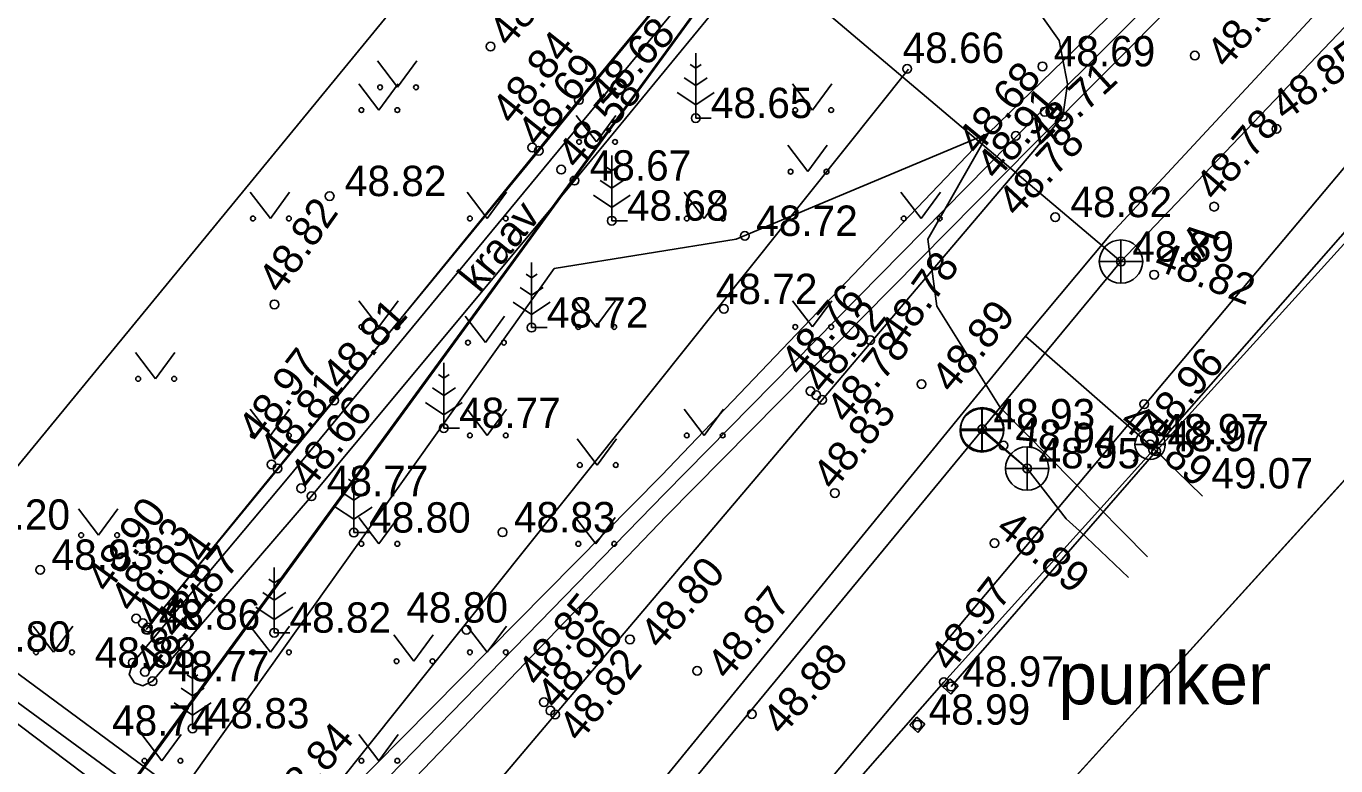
# Model space of a CAD drawing. Extents: x 640876 to 641418, y 6455595 to 6456085.
# Drawn here: x 641190.78 to 641220.97, y 6455862.86 to 6455879.91 of the extents above; entities that cross this region are included whole.
import ezdxf

# ---------------------------------------------------------------- set-up
doc = ezdxf.new("R2010")
doc.units = 0
for name, color, linetype in [('AED', 7, 'Continuous'), ('HALJASTUS', 7, 'Continuous'), ('HOONE', 7, 'Continuous'), ('KKAEV', 7, 'Continuous'), ('KORGUS', 7, 'Continuous'), ('KTRASS', 7, 'Continuous'), ('MOOTKORG', 7, 'Continuous'), ('MOOTMPUNKT', 7, 'Continuous'), ('MOOTPIIR', 7, 'Continuous'), ('PIIR', 7, 'Continuous'), ('PUU', 7, 'Continuous'), ('SITRASS', 7, 'Continuous'), ('TEE', 7, 'Continuous'), ('TTRASS', 7, 'Continuous'), ('VEEKOGU', 7, 'Continuous'), ('VKAEV', 7, 'Continuous'), ('VTRASS', 7, 'Continuous')]:
    doc.layers.add(name, color=color, linetype=linetype)

msp = doc.modelspace()

# ---------------------------------------------------------------- linework, layer by layer
at = {"layer": 'AED'}
for p, q in [((641211.91, 6455864.679), (641212.074, 6455864.867)), ((641211.91, 6455864.679), (641212.098, 6455864.515)), ((641212.074, 6455864.867), (641212.262, 6455864.703)), ((641212.098, 6455864.515), (641212.262, 6455864.703)), ((641211.146, 6455863.796), (641211.31, 6455863.984)), ((641211.146, 6455863.796), (641211.334, 6455863.632)), ((641211.31, 6455863.984), (641211.498, 6455863.82)), ((641211.334, 6455863.632), (641211.498, 6455863.82))]:
    msp.add_line(p, q, dxfattribs=at)
msp.add_lwpolyline([(641221.825, 6455875.625), (641216.829, 6455870.111), (641212.099, 6455864.686)], dxfattribs=at)
at = {"layer": 'HALJASTUS'}
for p, q in [((641198.876, 6455879.109), (641199.339, 6455878.502)), ((641199.339, 6455878.502), (641199.785, 6455879.109)), ((641198.445, 6455878.583), (641198.909, 6455877.977)), ((641198.909, 6455877.977), (641199.354, 6455878.583)), ((641208.445, 6455878.583), (641208.909, 6455877.977)), ((641208.909, 6455877.977), (641209.354, 6455878.583)), ((641203.462, 6455877.849), (641203.926, 6455877.242)), ((641203.926, 6455877.242), (641204.371, 6455877.849)), ((641208.338, 6455877.164), (641208.802, 6455876.557)), ((641208.802, 6455876.557), (641209.247, 6455877.164)), ((641195.945, 6455876.083), (641196.409, 6455875.477)), ((641196.409, 6455875.477), (641196.854, 6455876.083)), ((641200.945, 6455876.083), (641201.409, 6455875.477)), ((641201.409, 6455875.477), (641201.854, 6455876.083)), ((641205.945, 6455876.083), (641206.409, 6455875.477)), ((641206.409, 6455875.477), (641206.854, 6455876.083)), ((641210.945, 6455876.083), (641211.409, 6455875.477)), ((641211.409, 6455875.477), (641211.854, 6455876.083)), ((641198.445, 6455873.583), (641198.909, 6455872.977)), ((641198.909, 6455872.977), (641199.354, 6455873.583)), ((641203.445, 6455873.583), (641203.909, 6455872.977)), ((641203.909, 6455872.977), (641204.354, 6455873.583)), ((641208.445, 6455873.583), (641208.909, 6455872.977)), ((641208.909, 6455872.977), (641209.354, 6455873.583)), ((641200.901, 6455873.223), (641201.365, 6455872.616)), ((641201.365, 6455872.616), (641201.81, 6455873.223)), ((641193.299, 6455872.387), (641193.763, 6455871.781)), ((641193.763, 6455871.781), (641194.208, 6455872.387)), ((641195.945, 6455871.083), (641196.409, 6455870.477)), ((641196.409, 6455870.477), (641196.854, 6455871.083)), ((641200.945, 6455871.083), (641201.409, 6455870.477)), ((641201.409, 6455870.477), (641201.854, 6455871.083)), ((641205.945, 6455871.083), (641206.409, 6455870.477)), ((641206.409, 6455870.477), (641206.854, 6455871.083)), ((641203.48, 6455870.401), (641203.944, 6455869.794)), ((641203.944, 6455869.794), (641204.389, 6455870.401)), ((641191.986, 6455868.784), (641192.449, 6455868.177)), ((641192.449, 6455868.177), (641192.895, 6455868.784)), ((641198.445, 6455868.583), (641198.909, 6455867.977)), ((641198.909, 6455867.977), (641199.354, 6455868.583)), ((641203.445, 6455868.583), (641203.909, 6455867.977)), ((641203.909, 6455867.977), (641204.354, 6455868.583)), ((641190.945, 6455866.083), (641191.409, 6455865.477)), ((641191.409, 6455865.477), (641191.854, 6455866.083)), ((641195.945, 6455866.083), (641196.409, 6455865.477)), ((641196.409, 6455865.477), (641196.854, 6455866.083)), ((641199.256, 6455865.877), (641199.719, 6455865.271)), ((641199.719, 6455865.271), (641200.165, 6455865.877)), ((641200.945, 6455866.083), (641201.409, 6455865.477)), ((641201.409, 6455865.477), (641201.854, 6455866.083)), ((641193.445, 6455863.583), (641193.909, 6455862.977)), ((641193.909, 6455862.977), (641194.354, 6455863.583)), ((641198.445, 6455863.583), (641198.909, 6455862.977)), ((641198.909, 6455862.977), (641199.354, 6455863.583))]:
    msp.add_line(p, q, dxfattribs=at)
for centre in [(641198.938, 6455878.502), (641199.767, 6455878.502), (641198.508, 6455877.977), (641199.336, 6455877.977), (641208.508, 6455877.977), (641209.336, 6455877.977), (641203.525, 6455877.242), (641204.354, 6455877.242), (641208.401, 6455876.557), (641209.229, 6455876.557), (641196.008, 6455875.477), (641196.836, 6455875.477), (641201.008, 6455875.477), (641201.836, 6455875.477), (641206.008, 6455875.477), (641206.836, 6455875.477), (641211.008, 6455875.477), (641211.836, 6455875.477), (641198.508, 6455872.977), (641199.336, 6455872.977), (641203.508, 6455872.977), (641204.336, 6455872.977), (641208.508, 6455872.977), (641209.336, 6455872.977), (641200.964, 6455872.616), (641201.793, 6455872.616), (641193.362, 6455871.781), (641194.191, 6455871.781), (641196.008, 6455870.477), (641196.836, 6455870.477), (641201.008, 6455870.477), (641201.836, 6455870.477), (641206.008, 6455870.477), (641206.836, 6455870.477), (641203.543, 6455869.794), (641204.371, 6455869.794), (641192.048, 6455868.177), (641192.877, 6455868.177), (641198.508, 6455867.977), (641199.336, 6455867.977), (641203.508, 6455867.977), (641204.336, 6455867.977), (641191.008, 6455865.477), (641191.836, 6455865.477), (641196.008, 6455865.477), (641196.836, 6455865.477), (641199.318, 6455865.271), (641200.147, 6455865.271), (641201.008, 6455865.477), (641201.836, 6455865.477), (641193.508, 6455862.977), (641194.336, 6455862.977), (641198.508, 6455862.977), (641199.336, 6455862.977)]:
    msp.add_circle(centre, 0.055, dxfattribs=at)
at = {"layer": 'HOONE'}
msp.add_lwpolyline([(641149.742, 6455963.717), (641189.36, 6455931.349), (641178.797, 6455918.488), (641209.743, 6455893.117), (641188.509, 6455867.25), (641179.281, 6455874.809), (641167.4, 6455884.521), (641162.961, 6455888.191)], dxfattribs=at)
at = {"layer": 'KKAEV'}
for p, q in [((641216.017, 6455873.983), (641216.017, 6455874.983)), ((641215.517, 6455874.483), (641216.517, 6455874.483)), ((641212.81, 6455870.093), (641212.81, 6455871.093)), ((641212.819, 6455870.118), (641212.819, 6455871.118)), ((641212.31, 6455870.593), (641213.31, 6455870.593)), ((641212.319, 6455870.618), (641213.319, 6455870.618)), ((641213.851, 6455869.215), (641213.851, 6455870.215)), ((641213.351, 6455869.715), (641214.351, 6455869.715))]:
    msp.add_line(p, q, dxfattribs=at)
for centre in [(641216.017, 6455874.483), (641212.81, 6455870.593), (641212.819, 6455870.618), (641213.851, 6455869.715)]:
    msp.add_circle(centre, 0.5, dxfattribs=at)
at = {"layer": 'KORGUS'}
for centre in [(641201.486, 6455879.442), (641217.721, 6455879.232), (641211.088, 6455878.926), (641203.523, 6455878.209), (641214.258, 6455877.939), (641214.527, 6455877.902), (641206.213, 6455877.792), (641214.674, 6455877.825), (641219.599, 6455877.542), (641213.592, 6455877.382), (641202.447, 6455877.113), (641202.594, 6455877.038), (641203.114, 6455876.603), (641203.419, 6455876.35), (641197.776, 6455875.993), (641218.162, 6455875.75), (641214.502, 6455875.508), (641204.278, 6455875.427), (641207.347, 6455875.076), (641216.779, 6455874.182), (641196.501, 6455873.497), (641206.865, 6455873.393), (641202.431, 6455872.961), (641210.235, 6455872.675), (641211.418, 6455871.659), (641197.878, 6455871.284), (641208.859, 6455871.496), (641208.994, 6455871.405), (641209.127, 6455871.296), (641216.554, 6455871.196), (641200.41, 6455870.647), (641213.306, 6455870.244), (641216.758, 6455870.138), (641196.438, 6455869.807), (641196.571, 6455869.717), (641197.119, 6455869.257), (641209.421, 6455869.149), (641197.36, 6455869.076), (641198.335, 6455868.236), (641201.763, 6455868.243), (641213.1, 6455867.995), (641191.105, 6455867.378), (641193.315, 6455866.255), (641193.472, 6455866.148), (641193.547, 6455866), (641193.585, 6455866.047), (641196.5, 6455865.929), (641200.932, 6455865.997), (641204.699, 6455865.775), (641193.238, 6455865.238), (641193.519, 6455865.029), (641206.247, 6455865.05), (641193.694, 6455864.808), (641211.935, 6455864.789), (641202.716, 6455864.327), (641202.864, 6455864.132), (641202.972, 6455864.043), (641207.507, 6455864.054), (641194.617, 6455863.722)]:
    msp.add_circle(centre, 0.1, dxfattribs=at)
at = {"layer": 'KTRASS'}
for p, q in [((641216.017, 6455874.483), (641207.241, 6455881.908)), ((641212.819, 6455870.618), (641216.017, 6455874.483)), ((641212.819, 6455870.618), (641213.854, 6455869.717))]:
    msp.add_line(p, q, dxfattribs=at)
for points in [[(641216.001, 6455874.47), (641231.848, 6455891.086), (641231.899, 6455887.222)], [(641199.925, 6455854.961), (641212.81, 6455870.593), (641213.851, 6455869.715), (641214.751, 6455868.557), (641215.062, 6455868.275), (641216.191, 6455867.2)]]:
    msp.add_lwpolyline(points, dxfattribs=at)
at = {"layer": 'MOOTMPUNKT'}
for centre in [(641214.205, 6455878.984), (641216.017, 6455874.483), (641212.819, 6455870.618), (641216.688, 6455870.271), (641216.829, 6455870.111), (641213.854, 6455869.717), (641193.574, 6455865.998), (641212.099, 6455864.686), (641211.322, 6455863.808)]:
    msp.add_circle(centre, 0.1, dxfattribs=at)
at = {"layer": 'MOOTPIIR'}
msp.add_lwpolyline([(641060.916, 6455895.936), (641100.061, 6455950.482), (641099.586, 6455952.159), (641069.132, 6455984.035), (641066.132, 6455988.623), (641076.463, 6456005.049), (641230.642, 6456010.048), (641237.36, 6455995.24), (641237.24, 6455992.81), (641236.258, 6455990.888), (641229.041, 6455971.315), (641203.026, 6455909.57), (641225.257, 6455906.847), (641239.512, 6455898.491), (641200.195, 6455851.697), (641192.016, 6455859.099), (641169.785, 6455829.138), (641192.025, 6455807.568), (641252.96, 6455758.075), (641231.388, 6455736.74), (641191.474, 6455775.975), (641152.419, 6455787.914), (641136.351, 6455788.307), (641049.066, 6455856.043)], dxfattribs=at)
at = {"layer": 'PIIR'}
for points in [[(641222.58, 6455998.61), (641237.36, 6455995.24), (641235.34, 6455991.29), (641228.11, 6455971.68), (641220.5, 6455953.19), (641213.41, 6455936.25), (641201.58, 6455908.74), (641224.93, 6455905.88), (641191.87, 6455860.58), (641157.02, 6455885.66), (641160.91, 6455891.99), (641102.26, 6455951.82), (641074.95, 6455979.64), (641084.84, 6455991.92)], [(641224.6, 6455873.24), (641239.42, 6455859.81), (641199.12, 6455815.36), (641184.3, 6455828.79)]]:
    msp.add_lwpolyline(points, close=True, dxfattribs=at)
msp.add_lwpolyline([(641315.35, 6455858.84), (641292.55, 6455879.89), (641262.53, 6455885.29), (641239.33, 6455889.47), (641203.18, 6455849.61), (641191.84, 6455860.59), (641224.93, 6455905.88), (641249.88, 6455902.84), (641270.69, 6455899.15), (641280.77, 6455915.37), (641291.33, 6455932.26), (641301.94, 6455948.72)], dxfattribs=at)
at = {"layer": 'PUU'}
for p, q in [((641206.213, 6455879.292), (641206.213, 6455877.792)), ((641206.213, 6455878.942), (641206.089, 6455879.024)), ((641206.338, 6455879.024), (641206.213, 6455878.942)), ((641206.213, 6455878.542), (641205.947, 6455878.719)), ((641206.48, 6455878.719), (641206.213, 6455878.542)), ((641205.789, 6455878.381), (641206.213, 6455878.098)), ((641206.213, 6455878.098), (641206.637, 6455878.381)), ((641206.573, 6455877.792), (641206.213, 6455877.792)), ((641204.278, 6455876.927), (641204.278, 6455875.427)), ((641204.278, 6455876.577), (641204.154, 6455876.66)), ((641204.402, 6455876.66), (641204.278, 6455876.577)), ((641204.278, 6455876.177), (641204.011, 6455876.355)), ((641204.545, 6455876.355), (641204.278, 6455876.177)), ((641203.854, 6455876.016), (641204.278, 6455875.733)), ((641204.278, 6455875.733), (641204.702, 6455876.016)), ((641204.638, 6455875.427), (641204.278, 6455875.427)), ((641202.431, 6455874.461), (641202.431, 6455872.961)), ((641202.431, 6455874.111), (641202.307, 6455874.194)), ((641202.556, 6455874.194), (641202.431, 6455874.111)), ((641202.431, 6455873.711), (641202.165, 6455873.888)), ((641202.698, 6455873.888), (641202.431, 6455873.711)), ((641202.007, 6455873.55), (641202.431, 6455873.267)), ((641202.431, 6455873.267), (641202.856, 6455873.55)), ((641202.791, 6455872.961), (641202.431, 6455872.961)), ((641200.41, 6455872.147), (641200.41, 6455870.647)), ((641200.41, 6455871.797), (641200.285, 6455871.88)), ((641200.534, 6455871.88), (641200.41, 6455871.797)), ((641200.41, 6455871.397), (641200.143, 6455871.575)), ((641200.677, 6455871.575), (641200.41, 6455871.397)), ((641199.986, 6455871.237), (641200.41, 6455870.954)), ((641200.41, 6455870.954), (641200.834, 6455871.237)), ((641200.77, 6455870.647), (641200.41, 6455870.647)), ((641198.335, 6455869.736), (641198.335, 6455868.236)), ((641198.335, 6455869.386), (641198.21, 6455869.469)), ((641198.459, 6455869.469), (641198.335, 6455869.386)), ((641198.335, 6455868.986), (641198.068, 6455869.164)), ((641198.601, 6455869.164), (641198.335, 6455868.986)), ((641197.91, 6455868.825), (641198.335, 6455868.543)), ((641198.335, 6455868.543), (641198.759, 6455868.825)), ((641198.695, 6455868.236), (641198.335, 6455868.236)), ((641196.5, 6455867.429), (641196.5, 6455865.929)), ((641196.5, 6455867.079), (641196.376, 6455867.162)), ((641196.625, 6455867.162), (641196.5, 6455867.079)), ((641196.5, 6455866.679), (641196.234, 6455866.856)), ((641196.767, 6455866.856), (641196.5, 6455866.679)), ((641196.076, 6455866.518), (641196.5, 6455866.235)), ((641196.5, 6455866.235), (641196.924, 6455866.518)), ((641196.86, 6455865.929), (641196.5, 6455865.929)), ((641194.617, 6455865.222), (641194.617, 6455863.722)), ((641194.617, 6455864.872), (641194.492, 6455864.955)), ((641194.741, 6455864.955), (641194.617, 6455864.872)), ((641194.617, 6455864.472), (641194.35, 6455864.65)), ((641194.883, 6455864.65), (641194.617, 6455864.472)), ((641194.192, 6455864.312), (641194.617, 6455864.029)), ((641194.617, 6455864.029), (641195.041, 6455864.312)), ((641194.977, 6455863.722), (641194.617, 6455863.722))]:
    msp.add_line(p, q, dxfattribs=at)
msp.add_lwpolyline([(641196.491, 6455860.595), (641211.119, 6455878.92)], dxfattribs=at)
at = {"layer": 'SITRASS'}
for points in [[(641160.717, 6455890.02), (641160.061, 6455889.202), (641160.124, 6455887.433), (641162.714, 6455885.215), (641168.31, 6455881.226), (641178.228, 6455873.851), (641188.611, 6455866.439), (641195.817, 6455861.122), (641198.143, 6455862.18), (641205.423, 6455869.555), (641212.959, 6455877.434), (641219.89, 6455884.166), (641222.806, 6455887.129), (641228.363, 6455892.82), (641230.103, 6455894.633)], [(641174.28, 6455868.6), (641175.337, 6455869.665), (641176.394, 6455870.73), (641176.446, 6455870.679), (641190.159, 6455860.476), (641192.86, 6455860.157), (641202.953, 6455874.327), (641207.15, 6455874.999), (641212.959, 6455877.434)], [(641212.959, 6455877.434), (641211.563, 6455875.001), (641211.77, 6455873.454), (641213.233, 6455871.118), (641216.627, 6455867.681)]]:
    msp.add_lwpolyline(points, dxfattribs=at)
at = {"layer": 'TEE'}
for points in [[(641206.263, 6455886.54), (641208.716, 6455884.516), (641206.865, 6455882.258), (641203.523, 6455878.209), (641197.878, 6455871.284), (641193.547, 6455866)], [(641196.58, 6455856.487), (641202.972, 6455864.043), (641209.127, 6455871.296), (641214.674, 6455877.825), (641214.783, 6455878.584), (641214.589, 6455879.582), (641214.19, 6455880.14), (641208.972, 6455884.583), (641206.409, 6455886.654)], [(641208.726, 6455884.52), (641202.594, 6455877.038), (641196.571, 6455869.717), (641193.585, 6455866.047)], [(641207.942, 6455860.242), (641211.935, 6455864.789), (641216.758, 6455870.138), (641221.631, 6455875.683)]]:
    msp.add_lwpolyline(points, dxfattribs=at)
at = {"layer": 'TTRASS'}
for points in [[(641146.983, 6455877.597), (641147.637, 6455878.312), (641148.076, 6455878.791), (641148.587, 6455879.349), (641156.827, 6455888.351), (641157.502, 6455889.088), (641158.299, 6455888.492), (641167.659, 6455881.582), (641177.2, 6455874.303), (641186.795, 6455867.097), (641195.745, 6455860.541), (641196.509, 6455859.853), (641197.119, 6455860.535), (641205.5, 6455869.137), (641213.939, 6455877.707), (641222.42, 6455886.169), (641230.878, 6455894.702), (641235.947, 6455899.687), (641236.146, 6455899.925), (641236.328, 6455899.987), (641239.542, 6455899.756)], [(641240.141, 6455899.285), (641236.489, 6455899.529), (641236.348, 6455899.464), (641230.948, 6455894.114), (641222.434, 6455885.667), (641213.976, 6455877.157), (641205.539, 6455868.624), (641197.23, 6455859.957), (641196.541, 6455859.328), (641186.928, 6455866.582), (641177.306, 6455873.752), (641167.696, 6455880.94), (641158.359, 6455887.923), (641157.562, 6455888.52), (641156.887, 6455887.782), (641148.647, 6455878.781), (641148.136, 6455878.223), (641147.697, 6455877.743), (641147.022, 6455877.006)]]:
    msp.add_lwpolyline(points, dxfattribs=at)
at = {"layer": 'VEEKOGU'}
msp.add_lwpolyline([(641193.238, 6455865.238), (641193.156, 6455864.969), (641193.28, 6455864.775), (641193.473, 6455864.706), (641193.694, 6455864.808), (641197.36, 6455869.076), (641203.419, 6455876.35), (641209.301, 6455883.508), (641209.392, 6455883.865), (641209.323, 6455884.072), (641209.13, 6455884.169), (641208.978, 6455884.183), (641208.764, 6455883.959), (641202.866, 6455876.823), (641196.797, 6455869.475), (641193.238, 6455865.238)], dxfattribs=at)
at = {"layer": 'VKAEV'}
for p, q in [((641216.338, 6455870.271), (641217.038, 6455870.271)), ((641216.441, 6455870.024), (641216.301, 6455869.884)), ((641216.935, 6455870.024), (641217.075, 6455869.884))]:
    msp.add_line(p, q, dxfattribs=at)
msp.add_circle((641216.688, 6455870.271), 0.35, dxfattribs=at)
at = {"layer": 'VTRASS'}
for points in [[(641213.817, 6455872.768), (641215.778, 6455875.106), (641223.644, 6455883.582), (641224.984, 6455884.848)], [(641198.833, 6455857.853), (641200.156, 6455858.831), (641202.364, 6455859.006), (641204.234, 6455861.028), (641213.817, 6455872.768), (641216.691, 6455870.253)], [(641216.691, 6455870.253), (641217.893, 6455869.077)]]:
    msp.add_lwpolyline(points, dxfattribs=at)

# ---------------------------------------------------------------- texts
at = {"layer": 'HOONE'}
msp.add_text('punker', height=1.2, dxfattribs=at).set_placement((641214.573, 6455864.278))
at = {"layer": 'KORGUS'}
for s, rotation, p in [(' 48.79', 50.4906, (641201.76, 6455879.194)), (' 48.82', 49.9795, (641218.293, 6455878.705)), (' 48.68', 46.8287, (641204.002, 6455877.803)), ('48.84', 51.4013, (641201.998, 6455877.606)), (' 48.85', 36.8232, (641219.599, 6455877.542)), ('48.69', 51.5407, (641202.59, 6455877.09)), ('48.68', 50.5275, (641212.718, 6455876.909)), (' 48.71', 42.7534, (641214.067, 6455876.868)), ('48.58', 49.527, (641203.489, 6455876.581)), ('48.91', 49.7807, (641213.152, 6455876.334)), ('48.78', 49.388, (641218.196, 6455875.846)), ('48.78', 47.0357, (641213.62, 6455875.478)), (' 48.82', 54.8486, (641196.501, 6455873.497)), (' 48.78', 54.4496, (641210.805, 6455872.268)), ('48.82', 338.6561, (641216.746, 6455874.324)), ('48.76', 49.8531, (641208.641, 6455871.804)), (' 48.81', 48.3906, (641197.878, 6455871.284)), ('48.92', 50.5279, (641209.156, 6455871.401)), (' 48.89', 50.5244, (641211.958, 6455871.214)), ('48.78', 50.2494, (641209.698, 6455870.713)), ('48.97', 52.5543, (641196.16, 6455870.27)), (' 48.96', 49.9559, (641216.758, 6455870.138)), ('48.81', 49.8088, (641196.623, 6455869.788)), ('48.66', 51.5295, (641197.335, 6455869.194)), ('48.83', 51.11, (641209.393, 6455869.175)), ('48.89', 320.7645, (641215.949, 6455870.734)), (' 48.94', 354.4471, (641213.306, 6455870.244)), ('48.90', 53.9679, (641192.667, 6455866.816)), ('48.89', 321.4311, (641213.095, 6455868.261)), ('48.83', 53.395, (641193.222, 6455866.361)), ('49.04', 53.904, (641193.801, 6455866.016)), (' 48.87', 50.5426, (641194.087, 6455865.555)), (' 48.80', 49.2163, (641205.229, 6455865.318)), ('48.74', 50.6634, (641193.75, 6455864.916)), (' 48.97', 52.0884, (641211.935, 6455864.789)), ('48.85', 50.9532, (641202.588, 6455864.651)), (' 48.87', 50.6259, (641206.788, 6455864.606)), ('48.96', 47.4358, (641202.995, 6455864.123)), (' 48.88', 48.5767, (641208.038, 6455863.334)), ('48.82', 51.1155, (641203.538, 6455863.375)), (' 48.84', 48.9689, (641196.669, 6455861.503))]:
    msp.add_text(s, height=0.7, rotation=rotation, dxfattribs=at).set_placement(p)
for s, p in [('48.66', (641210.983, 6455879.064)), ('48.65', (641206.563, 6455877.792)), ('48.67', (641203.769, 6455876.35)), ('48.82', (641198.126, 6455875.993)), ('48.68', (641204.628, 6455875.427)), ('48.82', (641214.852, 6455875.508)), (' 48.72', (641207.347, 6455875.076)), ('48.72', (641206.677, 6455873.504)), ('48.72', (641202.781, 6455872.961)), ('48.77', (641200.76, 6455870.647)), ('49.07', (641218.099, 6455869.254)), ('48.77', (641197.71, 6455869.076)), ('48.80', (641198.685, 6455868.236)), (' 48.83', (641201.763, 6455868.243)), (' 48.93', (641191.105, 6455867.378)), ('48.80', (641199.544, 6455866.162)), ('48.82', (641196.85, 6455865.929)), ('48.80', (641189.468, 6455865.491)), ('48.77', (641194.044, 6455864.808)), ('48.83', (641194.967, 6455863.722))]:
    msp.add_text(s, height=0.7, dxfattribs=at).set_placement(p)
at = {"layer": 'MOOTKORG'}
for s, p in [(' 48.69', (641214.205, 6455878.984)), (' 48.89', (641216.017, 6455874.483)), (' 48.93', (641212.819, 6455870.618)), (' 48.97', (641216.688, 6455870.271)), (' 48.97', (641216.829, 6455870.111)), (' 48.95', (641213.854, 6455869.717)), (' 52.20', (641189.189, 6455868.302)), (' 48.86', (641193.574, 6455865.998)), (' 48.88', (641192.101, 6455865.122)), (' 48.97', (641212.099, 6455864.686)), (' 48.99', (641211.322, 6455863.808)), (' 48.74', (641192.5, 6455863.554))]:
    msp.add_text(s, height=0.7, dxfattribs=at).set_placement(p)
at = {"layer": 'TEE'}
msp.add_text('A', height=0.7, rotation=51.1643, dxfattribs=at).set_placement((641217.91, 6455874.56))
at = {"layer": 'VEEKOGU'}
msp.add_text('kraav', height=0.7, rotation=50.964, dxfattribs=at).set_placement((641201.221, 6455873.743))

doc.saveas('drawing.dxf')
